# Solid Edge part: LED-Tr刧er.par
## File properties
Author: heha
Template: Normal.par
Last saved by: heha
Revision: 9
Application: Solid Edge
Dichte: 1,024 kg/dm^3
Genauigkeit: 0,990
Material: ABS Plastik, mittelfest
Teilflächenrmatvorlage: Schwarz
Füllformatvorlage: ANSI34(Plastic)
Virtuelle Formatvorlage: Schwarz (hell glänzend)
Coef. of Thermal Exp: 5.8e-05
Thermal Conductivity: 2.0
Specific Heat: 0.0
Modulus of Elasticity: 2275269810.0
Poission's Ratio: 0.4
Yield Stress: 43436969.1
Ultimate Stress: 0.0
Elongation: 0.0
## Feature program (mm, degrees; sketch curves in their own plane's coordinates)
sketch for "unnamed RevolvedProtrusion 1" plane through (0, 0, 0) normal (0, -1, 0) x-axis (1, 0, 0)
  line (-27.9, 0) -> (-3, 0)
  line (-3, 0) -> (-3, -3)
  line (-3, -3) -> (-8.9, -3)
  line (-8.9, -3) -> (-8.9, -5)
  line (-8.9, -5) -> (-22.6, -5)
  line (-22.6, -5) -> (-22.6, -12)
  line (-22.6, -12) -> (-27.9, -12)
  line (-27.9, -12) -> (-27.9, 0)
  dimension (linear) = 22.6
  dimension (linear) = 22.6
  dimension (linear) = 3
  dimension (linear) = 8.9
  dimension (linear) = 8.9
revolve "unnamed RevolvedProtrusion 1" add full turn 360 deg
sketch for "Bohrung_1" plane through (0, 0, 0) normal (0, 0, 1) x-axis (1, 0, 0)
  hole centre (-22.4744, -10.7197) bore radius 1.65
hole "Bohrung_1" diameter 3.3 through  CounterSinkAngle = 90 deg
sketch for "unnamed Hole 1" plane through (0, 0, 0) normal (0, 0, 1) x-axis (1, 0, 0)
  hole centre (22.4744, -10.7197) bore radius 1.65
hole "unnamed Hole 1" through
sketch for "unnamed Hole 2" plane through (0, 0, 0) normal (0, 0, 1) x-axis (1, 0, 0)
  hole centre (-8.5163, 23.3983) bore radius 1.65
hole "unnamed Hole 2" through
sketch for "Bohrung_4" plane through (0, 0, 0) normal (0, 0, 1) x-axis (1, 0, 0)
  hole centre (-24.5934, -3.8952) bore radius 1.65
hole "Bohrung_4" diameter 3.3 through
sketch for "unnamed Hole 3" plane through (0, 0, 0) normal (0, 0, 1) x-axis (1, 0, 0)
  hole centre (24.5934, 3.8952) bore radius 1.65
hole "unnamed Hole 3" through
sketch for "unnamed Hole 4" plane through (0, 0, 0) normal (0, 0, 1) x-axis (1, 0, 0)
  hole centre (-24.7882, 2.3569) bore radius 1.65
hole "unnamed Hole 4" through
sketch for "Vertiefung" plane through (0, 0, 0) normal (0, 0, 1) x-axis (1, 0, 0)
  line (-24.4441, 2.8484) -> (-8.2977, -8.4575)
  arc centre (-6.5769, -6) radius 3 from (-8.2977, -8.4575) to (-6.5769, -9) ccw
  line (-6.5769, -9) -> (3, -9)
  arc centre (3, -12) radius 3 from (3, -9) to (6, -12) cw
  line (6, -12) -> (6, -15)
  arc centre (0, -15) radius 6 from (6, -15) to (-6, -15) cw
  line (-6, -13.0929) -> (-6, -15)
  arc centre (-9, -13.0929) radius 3 from (-6, -13.0929) to (-7.2793, -10.6355) ccw
  line (-7.2793, -10.6355) -> (-25.1324, 1.8654)
  line (-25.1324, 1.8654) -> (-24.4441, 2.8484)
  dimension (linear) = 25.1324
extrude "Vertiefung" cut finite 3.2 along -normal
sketch for "Bohrung_7" plane through (0, 0, 0) normal (0, 0, 1) x-axis (1, 0, 0)
  hole centre (-1.5, -10.75) bore radius 1.1
hole "Bohrung_7" diameter 2.2 through
sketch for "unnamed Hole 5" plane through (0, 0, 0) normal (0, 0, 1) x-axis (1, 0, 0)
  hole centre (1.5, -10.75) bore radius 1.1
hole "unnamed Hole 5" through
sketch for "unnamed Hole 6" plane through (0, 0, 0) normal (0, 0, 1) x-axis (1, 0, 0)
  hole centre (1.5, -13.25) bore radius 1.1
hole "unnamed Hole 6" through
sketch for "unnamed Hole 7" plane through (0, 0, 0) normal (0, 0, 1) x-axis (1, 0, 0)
  hole centre (-1.5, -13.25) bore radius 1.1
hole "unnamed Hole 7" through
sketch for "unnamed Hole 8" plane through (0, 0, 0) normal (0, 0, 1) x-axis (1, 0, 0)
  hole centre (0, -15.75) bore radius 1.1
hole "unnamed Hole 8" through
sketch for "unnamed Hole 9" plane through (0, 0, 0) normal (0, 0, 1) x-axis (1, 0, 0)
  hole centre (0, -18.75) bore radius 1.1
hole "unnamed Hole 9" through
pattern "unnamed Pattern 1" of "Bohrung_7", "unnamed Hole 5", "unnamed Hole 6", "unnamed Hole 7", "unnamed Hole 8", "unnamed Hole 9"
pattern "unnamed Pattern 2" of "Bohrung_1", "unnamed Hole 1", "unnamed Hole 2"
pattern "unnamed Pattern 3" of "Bohrung_4", "unnamed Hole 3", "unnamed Hole 4"
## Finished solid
Body 1: solid body, 36 faces, 78 edges, 32 vertices.
  Faces by surface: cylinder 23, plane 10, cone 3
  Edges by curve: circle 49, line 26, intersection 3
Bounding box of the edges (mm): 55.800 x 55.800 x 12.000, from (-27.9, -27.9, -12) to (27.9, 27.9, 0).
Cylindrical faces by radius (mm): R1.1 x6, R1.65 x6, R3 x4, R3.1 x3, R6 x1, R8.9 x1, R22.6 x1, R27.9 x1
Conical faces (half-angle, radius in mm at the cone's reference point): 45 deg R3.1 x3
Planar faces by outward normal: +x 1, +z 2, -x 1, -y 1, -z 3, oblique 2
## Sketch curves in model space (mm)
circle centre (0, -15, 0) radius 5.75
line (0, -15, 0) -> (-24.7882, 2.3569, 0)
line (0, -15.75, 0) -> (0, -18.75, 0)
line (1.5, -10.75, 0) -> (1.5, -13.25, 0)
line (1.5, -13.25, 0) -> (-1.5, -13.25, 0)
line (-1.5, -13.25, 0) -> (-1.5, -10.75, 0)
line (-1.5, -10.75, 0) -> (1.5, -10.75, 0)
circle centre (0, 0, 0) radius 24.9
line (-24.5934, -3.8952, 0) -> (24.5934, 3.8952, 0)
line (-29.1296, -23.1, 0) -> (31.2229, -23.1, 0)
line (0, 0, 0) -> (-8.5163, 23.3983, 0)
line (0, 0, 0) -> (-22.4744, -10.7197, 0)
line (22.4744, -10.7197, 0) -> (-22.4744, -10.7197, 0)
line (0, 0, 0) -> (22.4744, -10.7197, 0)
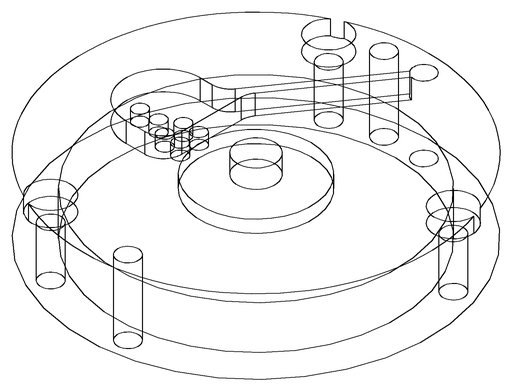
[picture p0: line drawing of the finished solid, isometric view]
